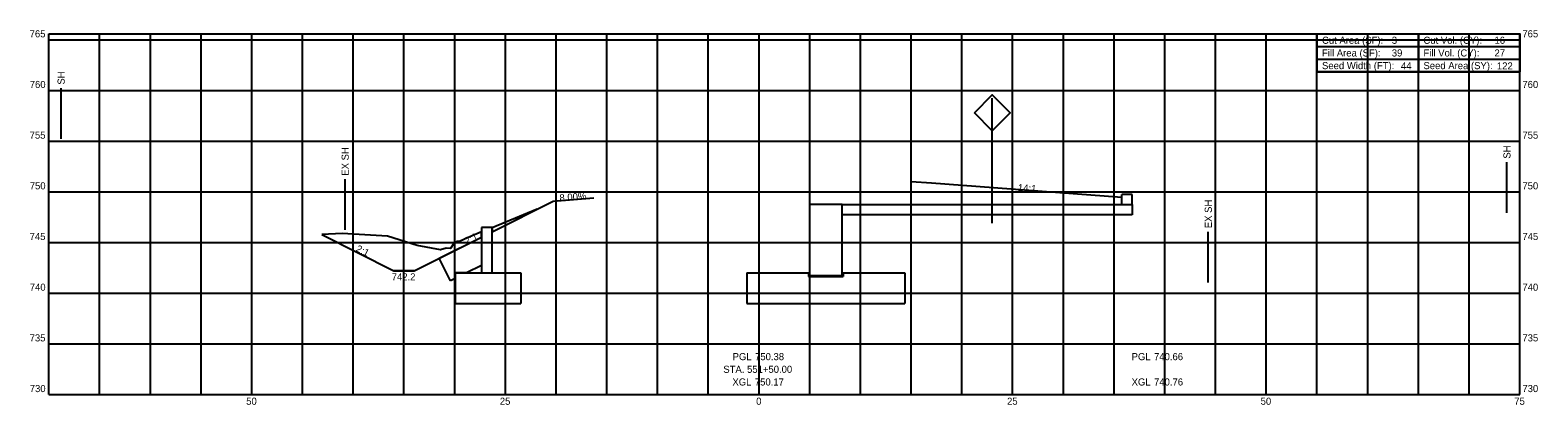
# Model space of a CAD drawing. Extents: x -72 to 77, y 729 to 766.
import ezdxf

# ---------------------------------------------------------------- set-up
doc = ezdxf.new("R2010")
doc.units = 0
for name, color, linetype in [('_CIVIL_CONSTRUCTION', 7, 'Continuous'), ('CM_Corridor_Range_Design', 7, 'Continuous'), ('CM_Corridor_Top_Mesh', 7, 'Continuous'), ('Default', 7, 'Continuous'), ('DR_P_Erosion_Control', 7, 'Continuous'), ('DT_P_Contour_Major', 7, 'Continuous'), ('DT_P_Contour_Minor', 7, 'Continuous'), ('DT_P_Tie', 7, 'Continuous'), ('DT_X_Spot_Elev', 7, 'Continuous'), ('MD_P_GRADE_BREAK', 7, 'Continuous'), ('MD_P_Surface_Aggregate_Base', 7, 'Continuous'), ('MD_P_Surface_Ditch', 7, 'Continuous'), ('MD_P_Surface_Finished_Grade', 7, 'Continuous'), ('MD_X_XGL', 7, 'Continuous'), ('PF_X_Ground_Line', 7, 'Continuous')]:
    doc.layers.add(name, color=color, linetype=linetype)

msp = doc.modelspace()

# ---------------------------------------------------------------- linework, layer by layer
at = {"layer": '_CIVIL_CONSTRUCTION'}
for p, q in [((55, 765.59), (75, 765.59)), ((55, 765.59), (55, 763.09)), ((65, 765.59), (65, 761.84)), ((75, 765.59), (75, 763.09)), ((55, 764.34), (75, 764.34)), ((55, 763.09), (75, 763.09)), ((63.3, 762.46), (63.3, 762.46)), ((72.95, 762.46), (72.95, 762.46))]:
    msp.add_line(p, q, dxfattribs=at)
msp.add_lwpolyline([(55, 763.09), (55, 761.84), (75, 761.84), (75, 763.09)], dxfattribs=at)
at = {"layer": 'CM_Corridor_Range_Design'}
for p, q in [((15, 751.04), (17, 750.88)), ((17, 750.88), (35.77, 749.47)), ((-26.32, 746.06), (-20.28, 749.08)), ((-20.28, 749.08), (-16.28, 749.4)), ((-43.11, 745.79), (-35.99, 742.23)), ((-43.11, 745.79), (-35.99, 742.23)), ((-33.99, 742.23), (-27.35, 745.54))]:
    msp.add_line(p, q, dxfattribs=at)
at = {"layer": 'CM_Corridor_Top_Mesh'}
for p, q in [((-40.8, 746.25), (-40.8, 751.25)), ((44.29, 741.07), (44.29, 746.07))]:
    msp.add_line(p, q, dxfattribs=at)
at = {"layer": 'Default'}
msp.add_circle((75, 765.59), 0.000417, dxfattribs=at)
msp.add_circle((75, 765.59), 0.000417, dxfattribs=at)
msp.add_circle((75, 765.59), 0.000417, dxfattribs=at)
msp.add_circle((75, 765.59), 0.000417, dxfattribs=at)
msp.add_circle((75, 765.59), 0.000417, dxfattribs=at)
msp.add_circle((75, 765.59), 0.000417, dxfattribs=at)
msp.add_circle((75, 765.59), 0.000417, dxfattribs=at)
msp.add_circle((75, 765.59), 0.000417, dxfattribs=at)
msp.add_circle((75, 765.59), 0.000417, dxfattribs=at)
msp.add_circle((75, 765.59), 0.000417, dxfattribs=at)
msp.add_circle((75, 765.59), 0.000417, dxfattribs=at)
msp.add_circle((75, 765.59), 0.000417, dxfattribs=at)
at = {"layer": 'DR_P_Erosion_Control'}
msp.add_lwpolyline([(55, 765.59), (75, 765.59), (75, 761.84), (55, 761.84)], close=True, dxfattribs=at)
at = {"layer": 'DT_P_Contour_Major'}
for p, q in [((-68.8, 755.23), (-68.8, 760.23)), ((73.73, 747.93), (73.73, 752.93))]:
    msp.add_line(p, q, dxfattribs=at)
at = {"layer": 'DT_P_Contour_Minor'}
for p, q in [((4.97, 748.75), (4.97, 741.75)), ((8.21, 748.75), (4.97, 748.75)), ((8.21, 741.75), (8.21, 748.75)), ((8.21, 748.75), (36.8, 748.75)), ((36.8, 747.75), (8.21, 747.75)), ((36.8, 748.75), (36.8, 747.75)), ((4.97, 741.75), (8.21, 741.75))]:
    msp.add_line(p, q, dxfattribs=at)
at = {"layer": 'DT_P_Tie'}
for p, q in [((35.77, 748.75), (35.77, 749.75)), ((36.8, 749.75), (35.77, 749.75)), ((36.8, 748.75), (36.8, 749.75)), ((-26.32, 746.5), (-27.35, 746.5)), ((-27.35, 746.5), (-27.35, 742)), ((-26.32, 742), (-26.32, 746.5))]:
    msp.add_line(p, q, dxfattribs=at)
at = {"layer": 'DT_X_Spot_Elev'}
for points in [[(-26.32, 746.47), (-26.32, 746.06), (-21.87, 748.29)], [(-43.11, 745.79), (-35.99, 742.23), (-33.99, 742.23), (-27.35, 745.54), (-27.35, 746.05), (-28.75, 745.48), (-29.47, 745.14), (-29.77, 745.1), (-30.12, 744.89), (-30.41, 744.42), (-30.85, 744.46), (-31.41, 744.27), (-33.69, 744.71), (-36.62, 745.64), (-41.1, 745.91)]]:
    msp.add_lwpolyline(points, close=True, dxfattribs=at)
at = {"layer": 'MD_P_GRADE_BREAK'}
for p, q in [((-31.53, 743.46), (-27.35, 745.54)), ((-27.35, 745.54), (-27.35, 742.75)), ((-30.41, 741.22), (-31.53, 743.46)), ((-28.85, 742), (-29.94, 742)), ((-29.94, 742), (-29.94, 741.46)), ((-27.35, 742.75), (-28.85, 742)), ((-29.94, 741.46), (-30.41, 741.22))]:
    msp.add_line(p, q, dxfattribs=at)
at = {"layer": 'MD_P_Surface_Aggregate_Base'}
msp.add_line((23, 746.93), (23, 759.26), dxfattribs=at)
msp.add_lwpolyline([(21.23, 757.8), (23, 759.57), (24.77, 757.8), (23, 756.04)], close=True, dxfattribs=at)
at = {"layer": 'MD_P_Surface_Finished_Grade'}
for p, q in [((-29.94, 742), (-29.94, 739)), ((-29.94, 742), (-23.47, 742)), ((-23.47, 742), (-23.47, 739)), ((-1.19, 742), (-1.19, 739)), ((-1.19, 742), (4.89, 742)), ((4.89, 742), (4.89, 741.67)), ((4.89, 741.67), (8.3, 741.67)), ((8.3, 742), (8.3, 741.67)), ((8.3, 742), (14.37, 742)), ((14.37, 742), (14.37, 739)), ((-29.94, 739), (-23.47, 739)), ((-1.19, 739), (14.37, 739))]:
    msp.add_line(p, q, dxfattribs=at)
at = {"layer": 'MD_X_XGL'}
for p, q in [((-70, 765.59), (75, 765.59)), ((-70, 730), (-70, 765.59)), ((-65, 730), (-65, 765.59)), ((-60, 730), (-60, 765.59)), ((-55, 730), (-55, 765.59)), ((-50, 730), (-50, 765.59)), ((-45, 730), (-45, 765.59)), ((-40, 730), (-40, 765.59)), ((-35, 730), (-35, 765.59)), ((-30, 730), (-30, 765.59)), ((-25, 730), (-25, 765.59)), ((-20, 730), (-20, 765.59)), ((-15, 730), (-15, 765.59)), ((-10, 730), (-10, 765.59)), ((-5, 730), (-5, 765.59)), ((0, 730), (0, 765.59)), ((5, 730), (5, 765.59)), ((10, 730), (10, 765.59)), ((15, 730), (15, 765.59)), ((20, 730), (20, 765.59)), ((25, 730), (25, 765.59)), ((30, 730), (30, 765.59)), ((35, 730), (35, 765.59)), ((40, 730), (40, 765.59)), ((45, 730), (45, 765.59)), ((50, 730), (50, 765.59)), ((55, 730), (55, 765.59)), ((60, 730), (60, 765.59)), ((65, 730), (65, 765.59)), ((70, 730), (70, 765.59)), ((75, 730), (75, 765.59)), ((-70, 765), (75, 765)), ((-70, 760), (75, 760)), ((-70, 755), (75, 755)), ((-70, 750), (75, 750)), ((-70, 745), (75, 745)), ((-70, 740), (75, 740)), ((-70, 735), (75, 735)), ((-70, 730), (75, 730))]:
    msp.add_line(p, q, dxfattribs=at)
at = {"layer": 'PF_X_Ground_Line'}
msp.add_line((-33.99, 742.23), (-35.99, 742.23), dxfattribs=at)

# ---------------------------------------------------------------- texts
at = {"layer": 'CM_Corridor_Top_Mesh'}
for p in [(-40.45, 751.6), (44.64, 746.42)]:
    msp.add_text('EX SH', height=0.7, rotation=90, dxfattribs=at).set_placement(p)
at = {"layer": 'DT_P_Contour_Major'}
for p in [(-68.45, 760.58), (74.08, 753.28)]:
    msp.add_text('SH', height=0.7, rotation=90, dxfattribs=at).set_placement(p)
at = {"layer": 'MD_P_Surface_Ditch'}
for s, p in [('765', (-71.9, 765.25)), ('765', (75.25, 765.25)), ('Cut Area (SF):', (55.5, 764.61)), ('Fill Area (SF):', (55.5, 763.36)), ('3', (62.38, 764.61)), ('39', (62.38, 763.36)), ('Cut Vol. (CY):', (65.5, 764.61)), ('Fill Vol. (CY):', (65.5, 763.36)), ('27', (72.5, 763.36)), ('16', (72.5, 764.61)), ('Seed Width (FT):', (55.5, 762.11)), ('44', (63.28, 762.08)), ('Seed Area (SY):', (65.5, 762.11)), ('122', (72.74, 762.08)), ('760', (-71.89, 760.25)), ('760', (75.25, 760.25)), ('755', (-71.9, 755.25)), ('755', (75.25, 755.25)), ('750', (-71.89, 750.25)), ('750', (75.25, 750.25)), ('745', (-71.9, 745.25)), ('745', (75.25, 745.25)), ('742.2', (-36.21, 741.27)), ('740', (-71.89, 740.25)), ('740', (75.25, 740.25)), ('735', (-71.9, 735.25)), ('735', (75.25, 735.25)), ('STA. 551+50.00', (-3.52, 732.15)), ('PGL ', (-2.6, 733.4)), ('750.38', (-0.39, 733.4)), ('PGL ', (36.73, 733.4)), ('740.66', (38.94, 733.4)), ('XGL ', (-2.62, 730.9)), ('750.17', (-0.41, 730.9)), ('XGL ', (36.73, 730.9)), ('740.76', (38.94, 730.9)), ('730', (-71.89, 730.25)), ('730', (75.25, 730.25)), ('50', (-50.55, 729)), ('25', (-25.55, 729)), ('0', (-0.28, 729)), ('25', (24.45, 729)), ('50', (49.45, 729)), ('75', (74.45, 729))]:
    msp.add_text(s, height=0.7, dxfattribs=at).set_placement(p)
for s, rotation, p in [('14:1', 355.7229, (25.5, 750.09)), ('8.00%', 4.5739, (-19.64, 749.05)), ('2:1', 333.4349, (-39.8, 744.18)), ('2:1', 26.5651, (-28.81, 744.79))]:
    msp.add_text(s, height=0.7, rotation=rotation, dxfattribs=at).set_placement(p)

doc.saveas('drawing.dxf')
